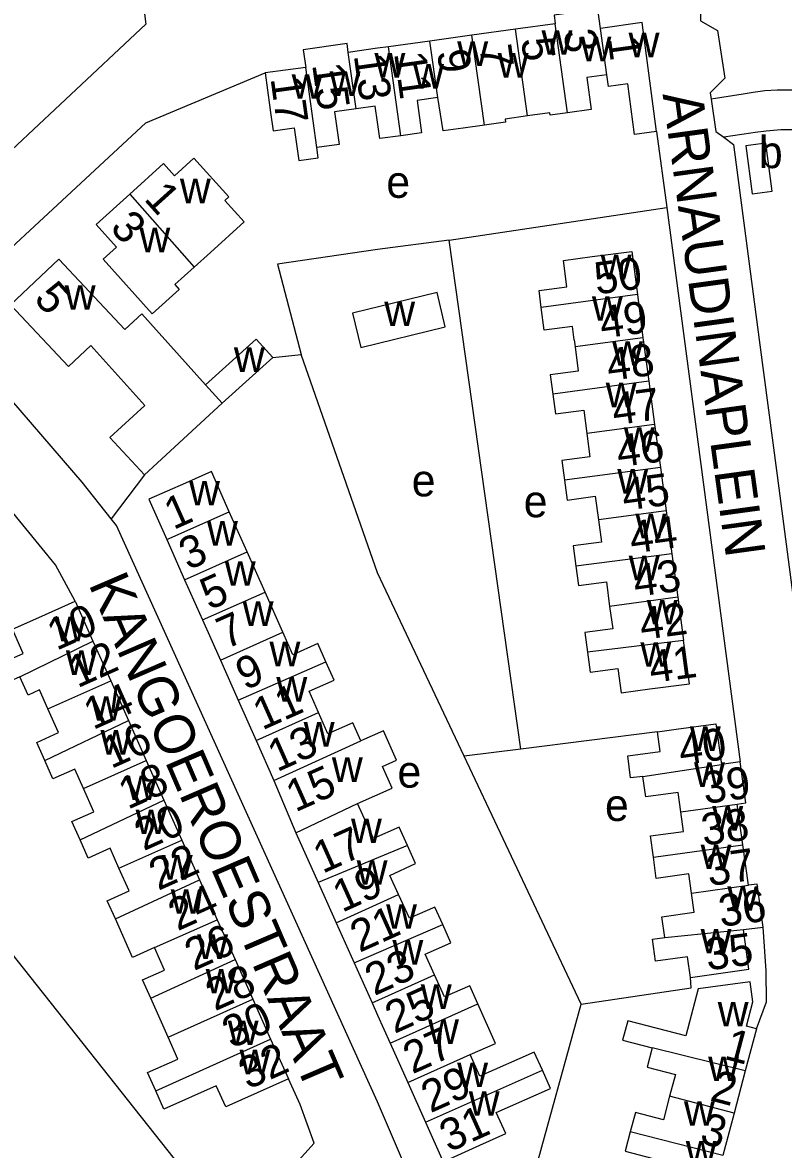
# Model space of a CAD drawing. Extents: x 162667 to 164645, y 379003 to 382150.
# Drawn here: x 163255.6 to 163350.8, y 381148.7 to 381289.7 of the extents above; entities that cross this region are included whole.
import ezdxf

# ---------------------------------------------------------------- set-up
doc = ezdxf.new("R2010")
doc.units = 0
for name, color, linetype in [('BLT_Basislijn', 7, 'Continuous'), ('BLT_Bebouwing', 7, 'Continuous'), ('BLT_Centroide', 7, 'Continuous'), ('BLT_Huisnummer', 7, 'Continuous'), ('BLT_Huisnummer_ tussenligend', 7, 'Continuous'), ('BLT_Onderverdeling_panden', 7, 'Continuous'), ('BLT_Straatnaam', 7, 'Continuous')]:
    doc.layers.add(name, color=color, linetype=linetype)

msp = doc.modelspace()

# ---------------------------------------------------------------- linework, layer by layer
at = {"layer": 'BLT_Basislijn'}
for p, q in [((163345.75, 381280.74), (163341.75, 381280.09)), ((163334.92, 381276.05), (163336.19, 381266.53)), ((163346.69, 381275.83), (163343.31, 381275.36)), ((163343.31, 381275.36), (163344.55, 381274.45)), ((163344.55, 381274.45), (163347.76, 381250)), ((163308.95, 381262.48), (163336.19, 381266.53)), ((163336.19, 381266.53), (163345.39, 381197.21)), ((163317.95, 381198.8), (163308.95, 381262.48)), ((163347.76, 381250), (163350, 381233)), ((163286.91, 381247.77), (163290.43, 381248.14)), ((163270.86, 381233.09), (163266.67, 381227.61)), ((163350, 381233), (163352.65, 381212.95)), ((163219.75, 381216.52), (163281.92, 381138.26)), ((163335.04, 381200.97), (163317.95, 381198.8)), ((163317.95, 381198.8), (163310.84, 381197.89))]:
    msp.add_line(p, q, dxfattribs=at)
for points in [[(163268.19, 381312), (163271.01, 381289.49), (163250.88, 381270.62), (163195.97, 381221.79)], [(163340.42, 381291.21), (163340.42, 381289.9), (163342.54, 381288.69), (163343.44, 381282.73), (163341.63, 381280.91), (163341.75, 381280.09)], [(163266.67, 381227.61), (163263.04, 381232.18), (163245.4, 381252.62), (163245.39, 381253.42), (163271.01, 381277.15), (163285.93, 381283.38)], [(163350, 381281.23), (163348.48, 381281.13), (163346.98, 381280.95), (163345.75, 381280.74)], [(163365.12, 381277.66), (163363.7, 381278.4), (163362.31, 381279.02), (163360.89, 381279.57), (163359.45, 381280.04), (163357.98, 381280.44), (163356.5, 381280.76), (163355, 381281), (163353.49, 381281.16), (163351.97, 381281.25), (163350.45, 381281.25), (163350, 381281.23)], [(163341.75, 381280.09), (163342.33, 381276.06), (163343.31, 381275.36)], [(163350, 381276.23), (163348.62, 381276.12), (163347.25, 381275.93), (163346.69, 381275.83)], [(163364.78, 381271.99), (163363.62, 381272.75), (163362.42, 381273.44), (163361.18, 381274.05), (163359.92, 381274.6), (163358.62, 381275.06), (163357.29, 381275.46), (163355.95, 381275.77), (163354.58, 381276.01), (163353.21, 381276.17), (163351.83, 381276.25), (163350.45, 381276.25), (163350, 381276.23)], [(163308.95, 381262.48), (163300, 381261.28), (163287.49, 381259.46), (163290.43, 381248.14)], [(163310.84, 381197.89), (163300, 381220.86), (163290.43, 381248.14)], [(163262.17, 381217.29), (163259.7, 381221.85), (163242.01, 381243.45), (163239.21, 381246.35), (163238.5, 381246.36), (163213.81, 381224.23)], [(163303.81, 381145.2), (163303.61, 381146.2), (163300, 381154.68), (163267.32, 381226.76), (163266.67, 381227.61)], [(163325.49, 381166.86), (163310.84, 381197.89)], [(163347.4, 381163.8), (163348.66, 381167.17), (163348.64, 381171.05), (163348.23, 381176.53)], [(163325.49, 381166.86), (163339.23, 381168.94), (163339.15, 381170.23)], [(163318.36, 381144.92), (163319.43, 381144.95), (163325.49, 381166.86)], [(163281.92, 381138.26), (163292.08, 381149.47), (163290.33, 381154.31), (163288.85, 381157.53)]]:
    msp.add_lwpolyline(points, dxfattribs=at)
at = {"layer": 'BLT_Bebouwing'}
for p, q in [((163322.24, 381289.54), (163317.26, 381288.85)), ((163311.81, 381288.1), (163306.56, 381287.37)), ((163317.26, 381288.85), (163311.81, 381288.1)), ((163306.56, 381287.37), (163301.36, 381286.65)), ((163291.01, 381284.08), (163285.93, 381283.38)), ((163285.93, 381283.38), (163286.52, 381279.05)), ((163332.51, 381255.66), (163333.21, 381250.24)), ((163324.59, 381250), (163324.71, 381249.11)), ((163333.21, 381250.24), (163333.25, 381250)), ((163333.25, 381250), (163333.94, 381244.83)), ((163286.91, 381247.77), (163280.57, 381242.05)), ((163333.94, 381244.83), (163334.67, 381239.42)), ((163280.57, 381242.05), (163270.86, 381233.09)), ((163334.67, 381239.42), (163335.39, 381234.02)), ((163335.39, 381234.02), (163336.12, 381228.61)), ((163283.68, 381223.46), (163281.45, 381228.49)), ((163336.12, 381228.61), (163336.84, 381223.2)), ((163273.62, 381225.01), (163275.86, 381219.98)), ((163285.92, 381218.44), (163283.68, 381223.46)), ((163336.84, 381223.2), (163337.57, 381217.79)), ((163275.86, 381219.98), (163278.09, 381214.96)), ((163262.17, 381217.29), (163264.39, 381212.31)), ((163288.15, 381213.41), (163285.92, 381218.44)), ((163337.57, 381217.79), (163338.3, 381212.38)), ((163278.09, 381214.96), (163280.33, 381209.93)), ((163264.39, 381212.31), (163266.61, 381207.33)), ((163280.33, 381209.93), (163282.57, 381204.9)), ((163266.61, 381207.33), (163268.84, 381202.35)), ((163282.57, 381204.9), (163284.8, 381199.88)), ((163268.84, 381202.35), (163271.06, 381197.37)), ((163284.8, 381199.88), (163287.04, 381194.85)), ((163271.06, 381197.37), (163273.28, 381192.39)), ((163345.39, 381197.21), (163343.02, 381196.88)), ((163346.1, 381192.05), (163345.39, 381197.21)), ((163273.28, 381192.39), (163275.51, 381187.41)), ((163345.01, 381191.9), (163346.1, 381192.05)), ((163345.71, 381186.8), (163345.01, 381191.9)), ((163275.51, 381187.41), (163277.73, 381182.43)), ((163346.4, 381181.75), (163345.71, 381186.8)), ((163277.73, 381182.43), (163279.95, 381177.45)), ((163292.56, 381182.1), (163294.82, 381177.07)), ((163279.95, 381177.45), (163282.18, 381172.47)), ((163294.82, 381177.07), (163297.07, 381172.06)), ((163345.78, 381176.2), (163348.23, 381176.53)), ((163282.18, 381172.47), (163284.4, 381167.49)), ((163297.07, 381172.06), (163299.32, 381167.04)), ((163284.4, 381167.49), (163286.62, 381162.51)), ((163347.4, 381163.8), (163346.01, 381158.52)), ((163286.62, 381162.51), (163288.85, 381157.53)), ((163301.57, 381162.02), (163303.79, 381157.07)), ((163346.01, 381158.52), (163344.62, 381153.23)), ((163303.79, 381157.07), (163306.02, 381152.11)), ((163344.62, 381153.23), (163343.22, 381147.94))]:
    msp.add_line(p, q, dxfattribs=at)
for points in [[(163327.9, 381288.96), (163327.57, 381291.36), (163322.1, 381290.61), (163322.24, 381289.54)], [(163334.92, 381276.05), (163333.11, 381289.68), (163327.9, 381288.96)], [(163296.34, 381285.96), (163296.18, 381287.05), (163290.7, 381286.29), (163291.01, 381284.08)], [(163301.36, 381286.65), (163300, 381286.47), (163296.34, 381285.96)], [(163328.7, 381283.16), (163326.17, 381282.81), (163326.72, 381278.81), (163323.78, 381278.4)], [(163334.92, 381276.05), (163332.15, 381275.68), (163331.31, 381282.02), (163328.9, 381281.69), (163328.7, 381283.16)], [(163302.9, 381275.53), (163300.29, 381275.17), (163300, 381277.23), (163299.72, 381279.24), (163297.31, 381278.91)], [(163307.54, 381280.31), (163304.95, 381279.95), (163305.51, 381275.89), (163302.9, 381275.53)], [(163313.37, 381276.85), (163310.71, 381276.48), (163308.21, 381276.14), (163307.54, 381280.31)], [(163286.52, 381279.05), (163286.61, 381278.44), (163286.92, 381276.14), (163289.58, 381276.5), (163290.15, 381272.42), (163292.57, 381272.75), (163292.4, 381274.04)], [(163297.31, 381278.91), (163294.62, 381278.53), (163295.19, 381274.43), (163292.4, 381274.04)], [(163318.76, 381278.01), (163315.97, 381277.62), (163316.02, 381277.22), (163313.37, 381276.85)], [(163323.78, 381278.4), (163321.6, 381278.1), (163321.56, 381278.39), (163318.76, 381278.01)], [(163269, 381268.23), (163273.22, 381272.05), (163274.6, 381270.52), (163277.03, 381272.71), (163281.39, 381267.88), (163280.9, 381267.43), (163283.32, 381264.75), (163279.11, 381260.94), (163277.04, 381259.07)], [(163277.04, 381259.07), (163274.64, 381256.9), (163275.17, 381256.31), (163271.8, 381253.26), (163265.65, 381260.07), (163267.34, 381261.59), (163264.78, 381264.42), (163269, 381268.23)], [(163320.48, 381254.05), (163320.21, 381256.17), (163323.7, 381256.63), (163323.26, 381259.92), (163326.85, 381260.4), (163331.81, 381261.05), (163332.51, 381255.66)], [(163254.06, 381254.37), (163260.13, 381260.08), (163268.39, 381251.3)], [(163296.87, 381253.34), (163297.91, 381249.05), (163308.48, 381251.61), (163307.45, 381255.9), (163296.87, 381253.34)], [(163270.86, 381233.09), (163266.52, 381237.79), (163270.89, 381241.79), (163264.13, 381249.28), (163261.32, 381246.64), (163254.06, 381254.37)], [(163324.59, 381250), (163324.38, 381251.68), (163320.85, 381251.22), (163320.48, 381254.05)], [(163268.39, 381251.3), (163270.52, 381253.23), (163278.47, 381244.37)], [(163278.47, 381244.37), (163284.81, 381250.09), (163286.91, 381247.77)], [(163324.71, 381249.11), (163325.12, 381246.07), (163321.61, 381245.6), (163321.93, 381243.2)], [(163321.93, 381243.2), (163322.27, 381240.72), (163325.8, 381241.19), (163326.19, 381238.29)], [(163326.19, 381238.29), (163326.58, 381235.37), (163323.05, 381234.91), (163323.38, 381232.43)], [(163281.45, 381228.49), (163279.22, 381233.52), (163275.96, 381232.07), (163271.39, 381230.04), (163273.62, 381225.01)], [(163323.38, 381232.43), (163323.71, 381229.95), (163327.25, 381230.42), (163327.65, 381227.47)], [(163327.65, 381227.47), (163328.02, 381224.69), (163324.49, 381224.21), (163324.83, 381221.67)], [(163324.83, 381221.67), (163325.15, 381219.25), (163328.63, 381219.71), (163329.04, 381216.65)], [(163255.26, 381207.84), (163253.94, 381207.25), (163252.92, 381209.53), (163255.66, 381210.76), (163254.31, 381213.79), (163257.6, 381215.26), (163262.17, 381217.29)], [(163329.04, 381216.65), (163329.42, 381213.83), (163325.94, 381213.38), (163326.28, 381210.9)], [(163293.55, 381209.71), (163292.53, 381211.99), (163289.4, 381210.6), (163288.15, 381213.41)], [(163326.28, 381210.9), (163326.61, 381208.42), (163330.08, 381208.88), (163330.49, 381205.83), (163334.07, 381206.31), (163339.02, 381206.97), (163338.3, 381212.38)], [(163292.62, 381203.35), (163291.43, 381206.03), (163294.57, 381207.42), (163293.55, 381209.71)], [(163258.76, 381203.83), (163257.7, 381206.19), (163256.28, 381205.55), (163255.26, 381207.84)], [(163258.37, 381197.35), (163257.35, 381199.63), (163260.09, 381200.85), (163258.76, 381203.83)], [(163297.93, 381199.81), (163296.92, 381202.09), (163293.8, 381200.7), (163292.62, 381203.35)], [(163335.04, 381200.97), (163337.37, 381201.29), (163342.32, 381201.97), (163343.02, 381196.88)], [(163297.51, 381191.99), (163301.82, 381193.92), (163300.62, 381196.62), (163302.37, 381197.4), (163300.74, 381201.07), (163297.93, 381199.81)], [(163333.21, 381195.38), (163331.67, 381195.18), (163331.31, 381197.95), (163335.38, 381198.51), (163335.04, 381200.97)], [(163263.21, 381193.86), (163262.12, 381196.29), (163259.39, 381195.06), (163258.37, 381197.35)], [(163287.04, 381194.85), (163289.77, 381188.32)], [(163337.96, 381190.93), (163337.62, 381193.38), (163333.56, 381192.82), (163333.21, 381195.38)], [(163262.79, 381187.44), (163261.77, 381189.73), (163264.51, 381190.95), (163263.21, 381193.86)], [(163303.74, 381186.74), (163302.72, 381189.03), (163299.48, 381187.59), (163297.51, 381191.99)], [(163334.51, 381185.26), (163334.15, 381187.92), (163338.3, 381188.49), (163337.96, 381190.93)], [(163289.77, 381188.32), (163292.56, 381182.1)], [(163267.65, 381183.91), (163266.55, 381186.38), (163263.81, 381185.16), (163262.79, 381187.44)], [(163302.62, 381180.58), (163301.54, 381182.99), (163304.76, 381184.46), (163303.74, 381186.74)], [(163339.28, 381180.77), (163338.95, 381183.17), (163334.88, 381182.61), (163334.51, 381185.26)], [(163267.21, 381177.54), (163266.19, 381179.82), (163268.93, 381181.05), (163267.65, 381183.91)], [(163308.15, 381176.83), (163307.18, 381179.01), (163304, 381177.65), (163302.62, 381180.58)], [(163335.94, 381175.2), (163335.58, 381177.82), (163339.61, 381178.37), (163339.28, 381180.77)], [(163348.23, 381176.53), (163347.49, 381181.9), (163346.4, 381181.75)], [(163272.1, 381173.95), (163272.1, 381173.95), (163269.36, 381172.72), (163267.21, 381177.54)], [(163307.12, 381170.55), (163305.97, 381173.12), (163309.17, 381174.55), (163308.15, 381176.83)], [(163339.15, 381170.23), (163338.8, 381172.79), (163334.79, 381172.24), (163334.41, 381174.99), (163335.94, 381175.2)], [(163339.15, 381170.23), (163341.51, 381170.55), (163346.46, 381171.24), (163345.78, 381176.2)], [(163271.63, 381167.64), (163270.61, 381169.92), (163273.35, 381171.14), (163272.1, 381173.95)], [(163312.56, 381166.91), (163311.55, 381169.19), (163308.37, 381167.78), (163307.12, 381170.55)], [(163347.4, 381163.8), (163346.17, 381164.13), (163346.97, 381167.16), (163346.63, 381169.69), (163341.67, 381169.01), (163340.12, 381168.8), (163338.56, 381162.9), (163331.31, 381164.8), (163330.67, 381162.39), (163334.38, 381161.41)], [(163273.81, 381162.76), (163271.63, 381167.64)], [(163299.32, 381167.04), (163300, 381165.52), (163301.57, 381162.02)], [(163311.6, 381160.58), (163314.77, 381161.95), (163312.56, 381166.91)], [(163272.24, 381156.03), (163271.22, 381158.31), (163275.01, 381160), (163273.81, 381162.76)], [(163320.62, 381158.61), (163319.6, 381160.89), (163312.81, 381157.88), (163311.6, 381160.58)], [(163334.38, 381161.41), (163333.74, 381159), (163337.27, 381158.07), (163336.55, 381155.35)], [(163306.02, 381152.11), (163308.23, 381147.17), (163312.8, 381149.22), (163316.04, 381150.68), (163314.86, 381153.31), (163321.64, 381156.33), (163320.62, 381158.61)], [(163288.85, 381157.53), (163281, 381154.02), (163279.81, 381156.67), (163273.26, 381153.74), (163272.24, 381156.03)], [(163336.55, 381155.35), (163335.77, 381152.41), (163332.26, 381153.33), (163331.63, 381150.91)], [(163331.63, 381150.91), (163330.99, 381148.49), (163334.49, 381147.58), (163333.75, 381144.77)]]:
    msp.add_lwpolyline(points, dxfattribs=at)
msp.add_lwpolyline([(163346.07, 381274.26), (163346.87, 381268.26), (163349.38, 381268.6), (163348.58, 381274.59)], close=True, dxfattribs=at)
at = {"layer": 'BLT_Onderverdeling_panden'}
for p, q in [((163323.78, 381278.4), (163322.24, 381289.54)), ((163313.37, 381276.85), (163311.81, 381288.1)), ((163318.76, 381278.01), (163317.26, 381288.85)), ((163328.7, 381283.16), (163327.9, 381288.96)), ((163302.9, 381275.53), (163301.36, 381286.65)), ((163307.54, 381280.31), (163306.56, 381287.37)), ((163297.31, 381278.91), (163296.34, 381285.96)), ((163292.4, 381274.04), (163291.01, 381284.08)), ((163269, 381268.23), (163277.04, 381259.07)), ((163332.51, 381255.66), (163320.48, 381254.05)), ((163333.21, 381250.24), (163324.71, 381249.11)), ((163278.47, 381244.37), (163280.57, 381242.05)), ((163333.94, 381244.83), (163321.93, 381243.2)), ((163334.67, 381239.42), (163326.19, 381238.29)), ((163335.39, 381234.02), (163323.38, 381232.43)), ((163273.62, 381225.01), (163281.45, 381228.49)), ((163336.12, 381228.61), (163327.65, 381227.47)), ((163275.86, 381219.98), (163283.68, 381223.46)), ((163336.84, 381223.2), (163324.83, 381221.67)), ((163278.09, 381214.96), (163285.92, 381218.44)), ((163337.57, 381217.79), (163329.04, 381216.65)), ((163280.33, 381209.93), (163288.15, 381213.41)), ((163255.26, 381207.84), (163264.39, 381212.31)), ((163338.3, 381212.38), (163326.28, 381210.9)), ((163282.57, 381204.9), (163293.55, 381209.71)), ((163258.76, 381203.83), (163266.61, 381207.33)), ((163284.8, 381199.88), (163292.62, 381203.35)), ((163258.37, 381197.35), (163268.84, 381202.35)), ((163287.04, 381194.85), (163297.93, 381199.81)), ((163263.21, 381193.86), (163271.06, 381197.37)), ((163333.21, 381195.38), (163343.02, 381196.88)), ((163262.79, 381187.44), (163273.28, 381192.39)), ((163289.77, 381188.32), (163297.51, 381191.99)), ((163337.96, 381190.93), (163345.01, 381191.9)), ((163267.65, 381183.91), (163275.51, 381187.41)), ((163303.74, 381186.74), (163292.56, 381182.1)), ((163334.51, 381185.26), (163345.71, 381186.8)), ((163267.21, 381177.54), (163277.73, 381182.43)), ((163294.82, 381177.07), (163302.62, 381180.58)), ((163339.28, 381180.77), (163346.4, 381181.75)), ((163272.1, 381173.95), (163279.95, 381177.45)), ((163297.07, 381172.06), (163308.15, 381176.83)), ((163335.94, 381175.2), (163345.78, 381176.2)), ((163271.63, 381167.64), (163282.18, 381172.47)), ((163299.32, 381167.04), (163307.12, 381170.55)), ((163273.81, 381162.76), (163284.4, 381167.49)), ((163301.57, 381162.02), (163312.56, 381166.91)), ((163272.24, 381156.03), (163286.62, 381162.51)), ((163346.01, 381158.52), (163334.38, 381161.41)), ((163303.79, 381157.07), (163311.6, 381160.58)), ((163306.02, 381152.11), (163320.62, 381158.61)), ((163344.62, 381153.23), (163336.55, 381155.35)), ((163343.22, 381147.94), (163331.63, 381150.91))]:
    msp.add_line(p, q, dxfattribs=at)

# ---------------------------------------------------------------- texts
at = {"layer": 'BLT_Centroide'}
for s, p in [('w', (163320.52, 381285.66)), ('w', (163325.39, 381284.84)), ('w', (163331.41, 381285.34)), ('w', (163309.97, 381284.25)), ('w', (163299.61, 381282.81)), ('w', (163315.03, 381282.81)), ('w', (163294, 381280.5)), ('w', (163304.45, 381281.42)), ('w', (163289.25, 381280.16)), ('b', (163347.72, 381271.48)), ('e', (163301.1, 381267.76)), ('w', (163275.27, 381267.09)), ('w', (163270.2, 381260.95)), ('w', (163327.92, 381257.56)), ('w', (163260.86, 381253.75)), ('w', (163326.82, 381252.38)), ('w', (163300.84, 381251.71)), ('w', (163329.36, 381246.75)), ('w', (163282.03, 381245.97)), ('w', (163328.55, 381241.56)), ('w', (163330.81, 381235.97)), ('e', (163304.28, 381230.41)), ('w', (163330, 381230.75)), ('w', (163276.42, 381229.28)), ('e', (163318.29, 381227.8)), ('w', (163278.66, 381224.25)), ('w', (163332.27, 381225.16)), ('w', (163331.43, 381219.91)), ('w', (163280.89, 381219.22)), ('w', (163283.12, 381214.19)), ('w', (163333.69, 381214.38)), ('w', (163259.64, 381212.28)), ('w', (163286.48, 381209.16)), ('w', (163332.88, 381209.09)), ('w', (163261.01, 381208.06)), ('w', (163287.34, 381204.72)), ('w', (163264.12, 381202.34)), ('w', (163290.76, 381199.09)), ('w', (163265.34, 381198.09)), ('w', (163339.08, 381198.56)), ('w', (163294.29, 381194.69)), ('e', (163302.49, 381193.97)), ('w', (163339.6, 381194.06)), ('w', (163268.57, 381192.41)), ('e', (163328.46, 381189.8)), ('w', (163269.73, 381188.16)), ('w', (163341.88, 381188.59)), ('w', (163296.68, 381187.03)), ('w', (163340.42, 381183.78)), ('w', (163273, 381182.47)), ('w', (163297.39, 381181.81)), ('w', (163274.12, 381178.19)), ('w', (163343.77, 381178.56)), ('w', (163301.07, 381176.31)), ('w', (163340.42, 381173.22)), ('w', (163277.43, 381172.53)), ('w', (163301.86, 381171.84)), ('w', (163278.5, 381168.22)), ('w', (163305.41, 381166.28)), ('w', (163342.56, 381164.09)), ('w', (163281.25, 381161.75)), ('w', (163306.32, 381161.91)), ('w', (163282.73, 381158.12)), ('w', (163309.96, 381156.5)), ('w', (163341.36, 381157.25)), ('w', (163311.41, 381152.91)), ('w', (163338.34, 381151.66)), ('w', (163338.57, 381146.69))]:
    msp.add_text(s, height=4, dxfattribs=at).set_placement(p)
at = {"layer": 'BLT_Huisnummer'}
for s, rotation, p in [('5', 277.8794, (163317.95, 381287.6)), ('1', 277.8794, (163328.77, 381287.74)), ('9', 277.8794, (163307.43, 381286.11)), ('13', 277.8794, (163297.02, 381285.58)), ('17', 277.8794, (163286.6, 381282.7)), ('1', 312.0892, (163270.66, 381267.57)), ('3', 312.0979, (163266.4, 381263.92)), ('50', 7.6439, (163327.39, 381255.66)), ('5', 312.3394, (163256.87, 381255.04)), ('49', 7.6439, (163328.07, 381250.15)), ('48', 7.6439, (163328.94, 381244.85)), ('47', 7.6439, (163329.61, 381239.29)), ('46', 7.6439, (163330.17, 381234.05)), ('45', 7.6439, (163330.85, 381228.6)), ('1', 23.9734, (163274.46, 381226.18)), ('44', 7.6439, (163331.81, 381223.25)), ('43', 7.6439, (163332.27, 381217.83)), ('5', 23.9734, (163278.96, 381216.13)), ('10', 24.0619, (163259.83, 381211.07)), ('42', 7.6439, (163333.06, 381212.44)), ('41', 7.6439, (163334.24, 381207.05)), ('9', 23.9734, (163283.42, 381206.1)), ('14', 24.0619, (163264.4, 381201.15)), ('40', 7.8173, (163337.96, 381196.74)), ('18', 24.0619, (163268.75, 381191.18)), ('15', 23.9734, (163289.71, 381190.85)), ('39', 7.8173, (163340.96, 381191.92)), ('38', 7.8173, (163340.79, 381186.7)), ('17', 24.1659, (163293.12, 381183.17)), ('22', 24.0619, (163272.56, 381181.04)), ('37', 7.8173, (163341.47, 381181.65)), ('36', 7.8173, (163342.95, 381176.53)), ('21', 24.1659, (163297.74, 381173.29)), ('26', 24.0619, (163277.03, 381171.01)), ('35', 7.8173, (163341.3, 381171.08)), ('25', 24.1659, (163302.11, 381163.14)), ('1', 345.2361, (163343.23, 381160.06)), ('32', 24.0619, (163283.78, 381156.15)), ('2', 345.2361, (163341.46, 381154.87)), ('31', 24.1659, (163308.93, 381148.31)), ('3', 345.2361, (163340.17, 381149.54))]:
    msp.add_text(s, height=4, rotation=rotation, dxfattribs=at).set_placement(p)
at = {"layer": 'BLT_Huisnummer_ tussenligend'}
for s, rotation, p in [('3', 277.8794, (163323.27, 381288.65)), ('7', 277.8794, (163312.73, 381286.69)), ('11', 277.8794, (163302.06, 381285.83)), ('15', 277.8794, (163291.81, 381284.42)), ('3', 23.9734, (163276.31, 381221.13)), ('7', 23.9734, (163281.03, 381211.25)), ('12', 24.0619, (163262.45, 381206.38)), ('11', 23.9734, (163285.57, 381201.11)), ('16', 24.0619, (163266.66, 381196.28)), ('13', 23.9734, (163287.42, 381195.88)), ('20', 24.0619, (163270.74, 381186.01)), ('19', 24.1659, (163295.56, 381178.3)), ('24', 24.0619, (163274.98, 381175.99)), ('23', 24.1659, (163299.59, 381167.88)), ('28', 24.0619, (163279.65, 381165.97)), ('30', 24.0619, (163281.73, 381161.27)), ('27', 24.1659, (163304.36, 381158.09)), ('29', 24.1659, (163306.62, 381153.22))]:
    msp.add_text(s, height=4, rotation=rotation, dxfattribs=at).set_placement(p)
at = {"layer": 'BLT_Straatnaam'}
for s, rotation, p in [('ARNAUDINAPLEIN', 277.8062, (163335.66, 381280.73)), ('KANGOEROESTRAAT', 293.3116, (163263.79, 381219.46))]:
    msp.add_text(s, height=5, rotation=rotation, dxfattribs=at).set_placement(p)

doc.saveas('drawing.dxf')
